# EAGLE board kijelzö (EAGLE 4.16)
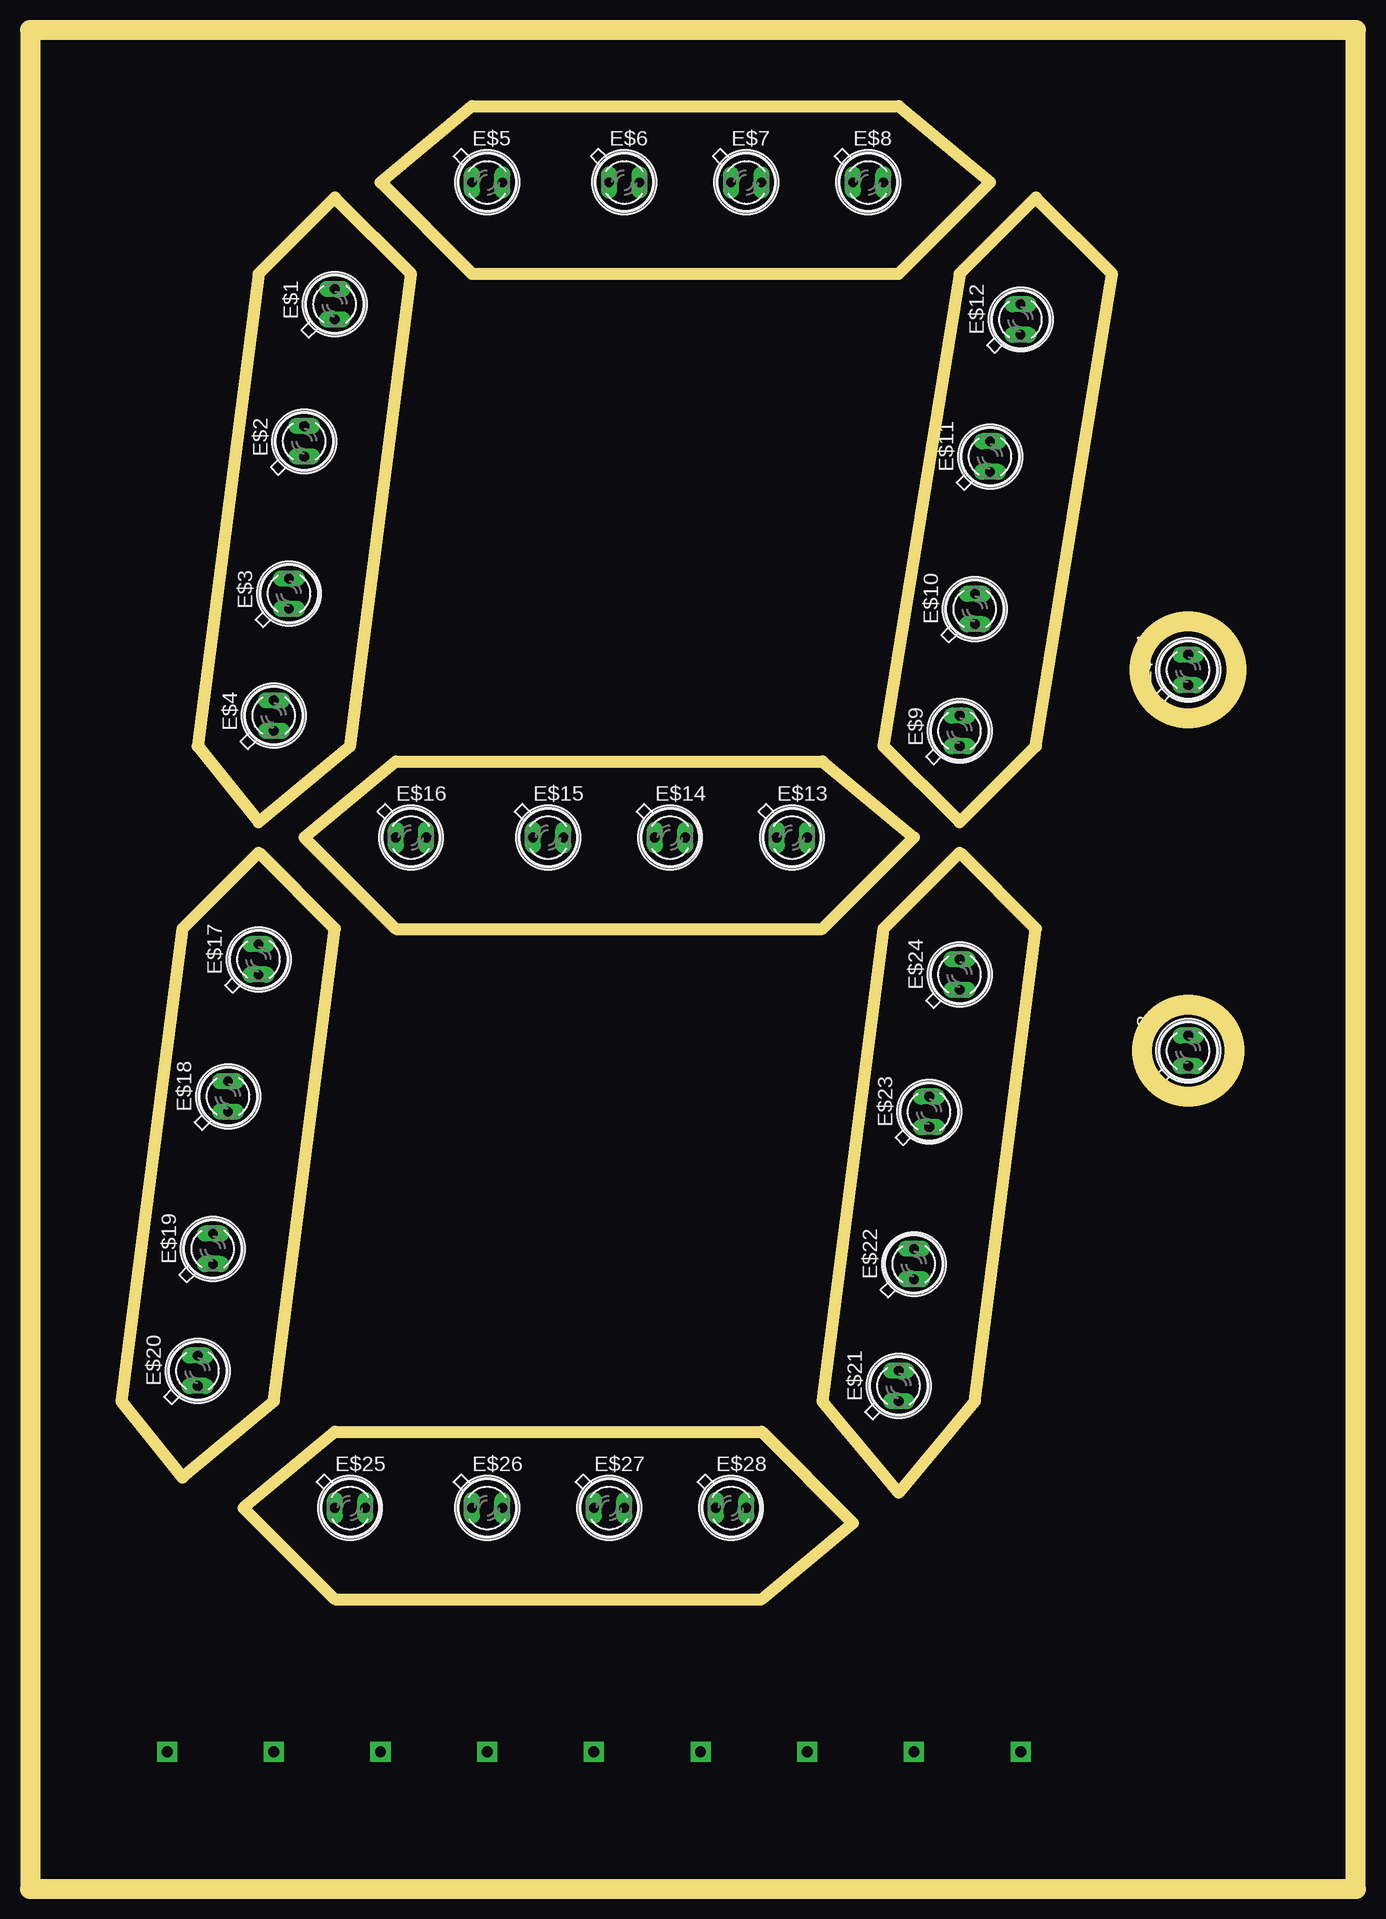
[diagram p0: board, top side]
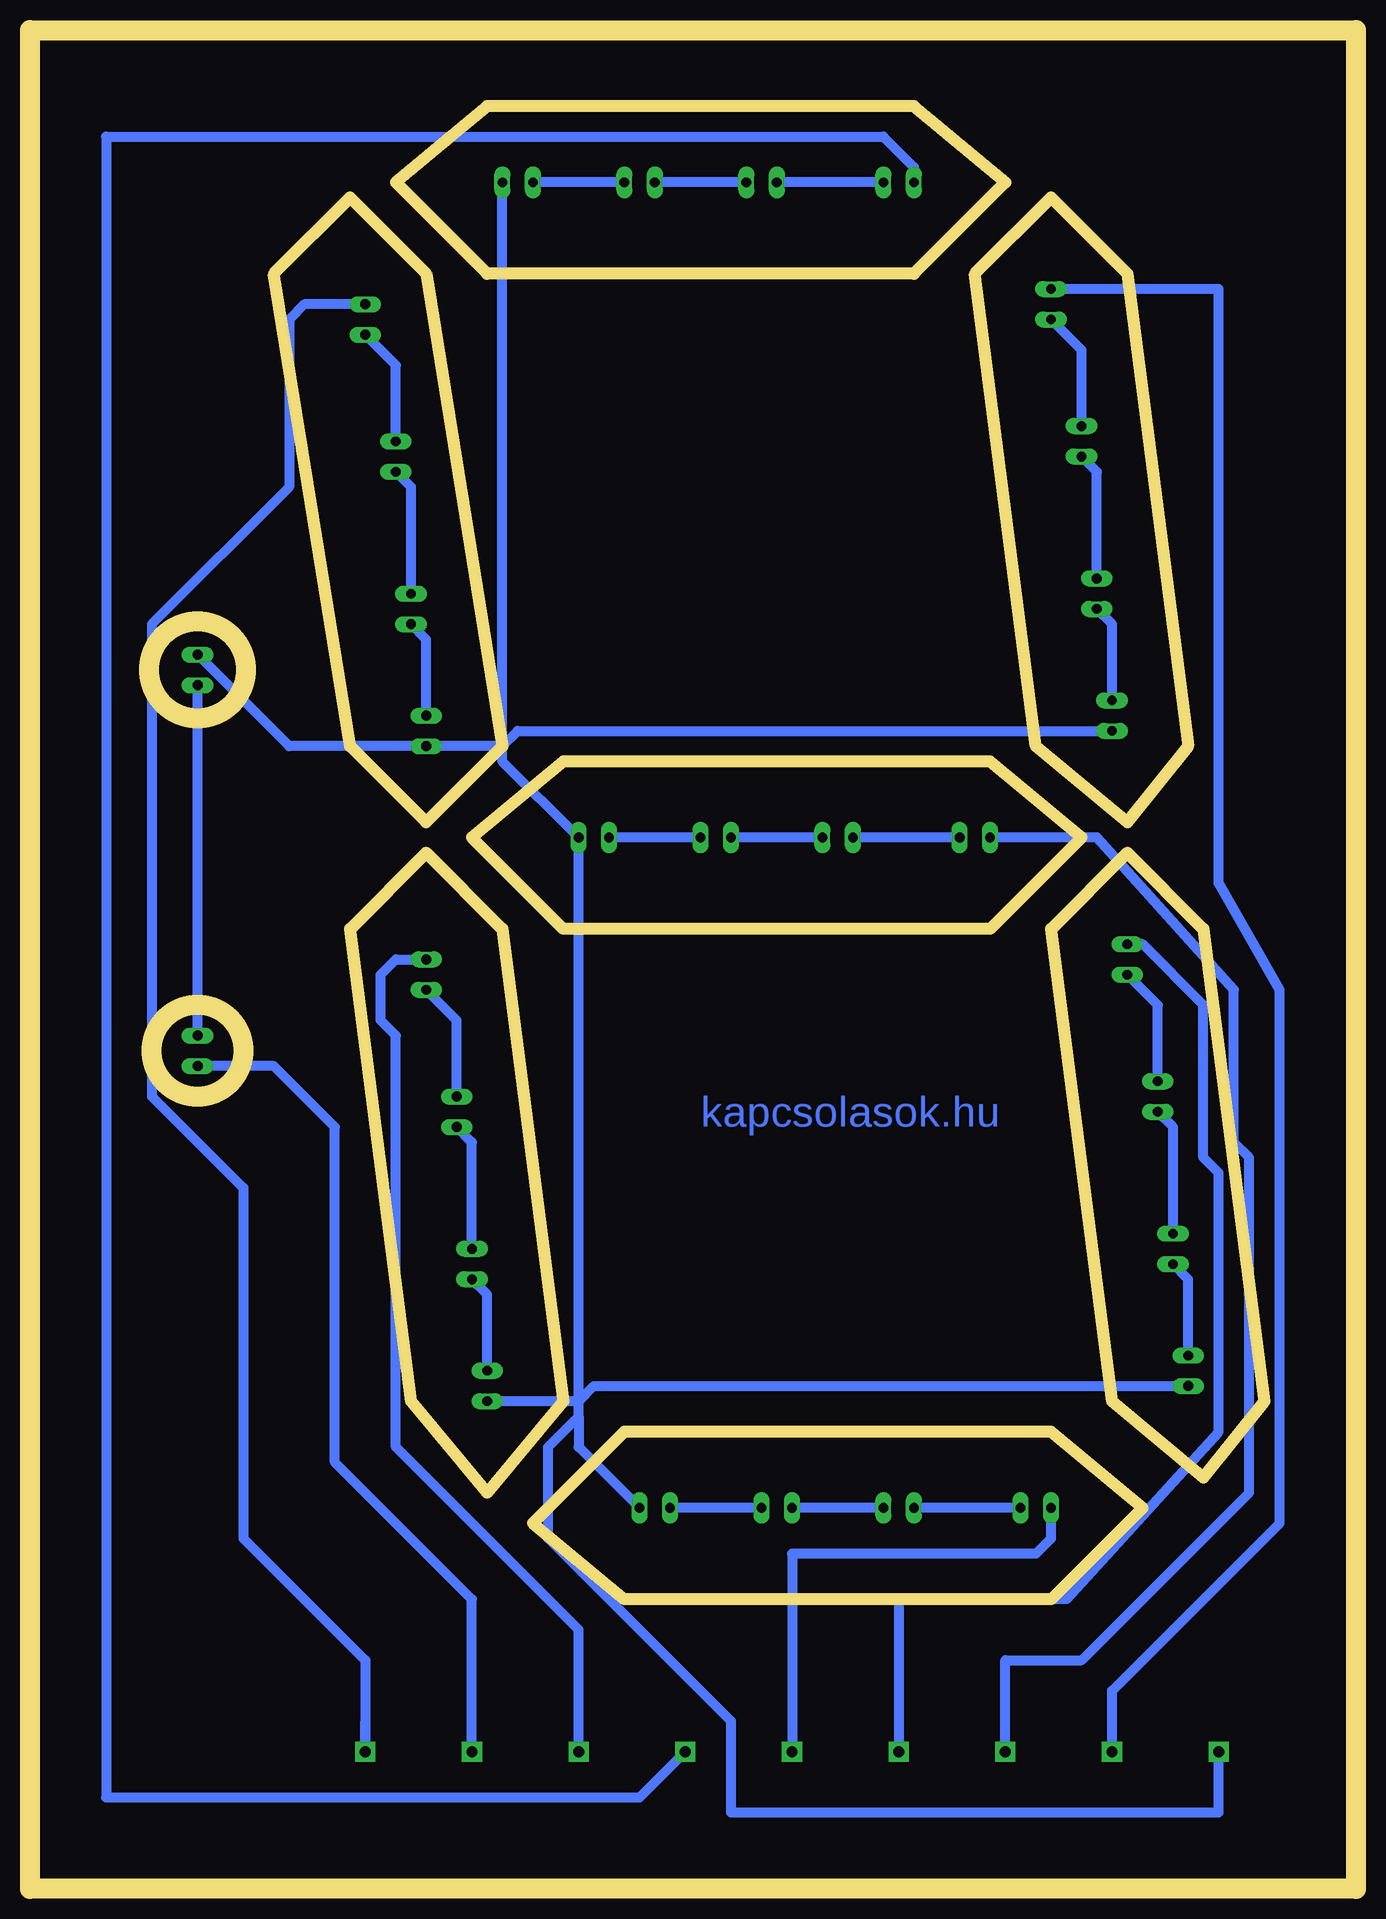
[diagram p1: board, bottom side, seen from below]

Size 110.49 x 154.94 mm. Coordinates in mm from the lower left corner, seen from the top.
Outline: 20.32,40.64 25.4,80.01 19.05,86.36 12.7,80.01 7.62,40.64 12.7,34.29 20.32,40.64
Outline: 26.67,95.25 31.75,134.62 25.4,140.97 19.05,134.62 13.97,95.25 19.05,88.9 26.67,95.25
Outline: 30.48,93.98 22.86,87.63 30.48,80.01 66.04,80.01 73.66,87.63 66.04,93.98 30.48,93.98
Outline: 78.74,40.64 83.82,80.01 77.47,86.36 71.12,80.01 66.04,40.64 72.39,33.02 78.74,40.64
Outline: 83.82,95.25 90.17,134.62 83.82,140.97 77.47,134.62 71.12,95.25 77.47,88.9 83.82,95.25
Outline: 36.83,148.59 29.21,142.24 36.83,134.62 72.39,134.62 80.01,142.24 72.39,148.59 36.83,148.59
Outline: 25.4,38.1 17.78,31.75 25.4,24.13 60.96,24.13 68.58,30.48 60.96,38.1 25.4,38.1
Outline: 0,0 110.49,0 110.49,154.94 0,154.94 0,0
Outline: circle at 96.52,101.6 radius 4.02
Outline: circle at 96.52,69.85 radius 3.81
Copper layers (1*16): Top 0.035mm / dielectric 1.5mm / Bottom 0.035mm
Design rules "default": minimum track width 10mil, minimum drill 24mil, track to track 8mil, track to pad 8mil, pad to pad 8mil, via to via 8mil, smd to smd 8mil, copper to edge 40mil, drill to drill 8mil, minimum pad ring 10mil, minimum via ring 8mil, stop-mask expansion 4mil, vias tented up to drill 0mil, thermal gap 10mil

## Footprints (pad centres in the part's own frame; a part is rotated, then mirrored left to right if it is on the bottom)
SFH480 = drill 0.813 long: A 1.27,0; K -1.27,0

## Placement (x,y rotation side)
E$1  [SFH480]  25.4,132.08 90 top
E$2  [SFH480]  22.86,120.65 90 top
E$3  [SFH480]  21.59,107.95 90 top
E$4  [SFH480]  20.32,97.79 90 top
E$5  [SFH480]  38.1,142.24 0 top
E$6  [SFH480]  49.53,142.24 0 top
E$7  [SFH480]  59.69,142.24 0 top
E$8  [SFH480]  69.85,142.24 0 top
E$9  [SFH480]  77.47,96.52 90 top
E$10  [SFH480]  78.74,106.68 90 top
E$11  [SFH480]  80.01,119.38 90 top
E$12  [SFH480]  82.55,130.81 90 top
E$13  [SFH480]  63.5,87.63 0 top
E$14  [SFH480]  53.34,87.63 0 top
E$15  [SFH480]  43.18,87.63 0 top
E$16  [SFH480]  31.75,87.63 0 top
E$17  [SFH480]  19.05,77.47 90 top
E$18  [SFH480]  16.51,66.04 90 top
E$19  [SFH480]  15.24,53.34 90 top
E$20  [SFH480]  13.97,43.18 90 top
E$21  [SFH480]  72.39,41.91 90 top
E$22  [SFH480]  73.66,52.07 90 top
E$23  [SFH480]  74.93,64.77 90 top
E$24  [SFH480]  77.47,76.2 90 top
E$25  [SFH480]  26.67,31.75 0 top
E$26  [SFH480]  38.1,31.75 0 top
E$27  [SFH480]  48.26,31.75 0 top
E$28  [SFH480]  58.42,31.75 0 top
E$33  [SFH480]  96.52,69.85 90 top
E$34  [SFH480]  96.52,101.6 90 top

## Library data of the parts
E$1-E$28 E$33 E$34 = led

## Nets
S$23: E$33.A E$34.K
S$28: E$33.K
S$37: E$12.A

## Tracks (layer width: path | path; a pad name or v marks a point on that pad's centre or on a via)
S$1
  Bottom 0.813: 27.94,31.75 36.83,31.75
S$2
  Bottom 0.813: 39.37,31.75 46.99,31.75
S$3
  Bottom 0.813: 49.53,31.75 57.15,31.75
S$4
  Bottom 0.813: 33.02,87.63 41.91,87.63
S$5
  Bottom 0.813: 44.45,87.63 52.07,87.63
S$6
  Bottom 0.813: 54.61,87.63 62.23,87.63
S$7
  Bottom 0.813: 39.37,142.24 48.26,142.24
S$8
  Bottom 0.813: 50.8,142.24 58.42,142.24
S$9
  Bottom 0.813: 60.96,142.24 68.58,142.24
S$10
  Bottom 0.813: 77.47,97.79 77.47,104.14 78.74,105.41
S$11
  Bottom 0.813: 78.74,107.95 78.74,116.84 80.01,118.11
S$12
  Bottom 0.813: 80.01,120.65 80.01,127 82.55,129.54
S$13
  Bottom 0.813: 20.32,99.06 20.32,105.41 21.59,106.68
S$14
  Bottom 0.813: 21.59,109.22 21.59,118.11 22.86,119.38
S$15
  Bottom 0.813: 22.86,121.92 22.86,128.27 25.4,130.81
S$16
  Bottom 0.813: 13.97,44.45 13.97,50.8 15.24,52.07
S$17
  Bottom 0.813: 15.24,54.61 15.24,63.5 16.51,64.77
S$18
  Bottom 0.813: 16.51,67.31 16.51,73.66 19.05,76.2
S$19
  Bottom 0.813: 72.39,43.18 72.39,49.53 73.66,50.8
S$20
  Bottom 0.813: 73.66,53.34 73.66,62.23 74.93,63.5
S$21
  Bottom 0.813: 74.93,66.04 74.93,72.39 77.47,74.93
S$22  (via drill 0.9 pad 1.68)
  Bottom 0.813: 71.12,95.25 71.12,142.24 | 71.12,95.25 71.12,93.98 64.77,87.63 64.77,40.64 | 64.77,39.37 64.77,40.64 | 64.77,39.37 64.77,36.83 59.69,31.75 | 64.77,40.64 72.39,40.64 | 20.32,96.52 69.85,96.52 71.12,95.25 | 13.97,41.91 63.5,41.91 64.77,40.64 | 71.12,95.25 88.9,95.25 96.52,102.87 | v11.43,11.43 11.43,6.35 52.07,6.35 52.07,13.97 67.31,29.21 67.31,36.83 64.77,39.37
S$23
  Bottom 0.813: E$33.A E$34.K
S$25  (via drill 0.9 pad 1.68)
  Bottom 0.813: 25.4,133.35 11.43,133.35 11.43,83.82 6.35,74.93 6.35,30.48 20.32,16.51 v20.32,11.43
S$26  (via drill 0.9 pad 1.68)
  Bottom 0.813: 30.48,87.63 21.59,87.63 10.16,74.93 10.16,62.23 8.89,60.96 8.89,33.02 22.86,19.05 29.21,19.05 v29.21,11.43
S$27  (via drill 0.9 pad 1.68)
  Bottom 0.813: v38.1,11.43 38.1,24.13 24.13,24.13 11.43,38.1 11.43,59.69 12.7,60.96 12.7,73.66 17.78,78.74 19.05,78.74
S$28  (via drill 0.9 pad 1.68)
  Bottom 0.813: v73.66,11.43 73.66,24.13 85.09,35.56 85.09,63.5 90.17,68.58 E$33.K
S$29  (via drill 0.9 pad 1.68)
  Bottom 0.813: v46.99,11.43 46.99,27.94 26.67,27.94 25.4,29.21 25.4,31.75
S$30  (via drill 0.9 pad 1.68)
  Bottom 0.813: 77.47,77.47 80.01,77.47 81.28,76.2 81.28,72.39 80.01,71.12 80.01,36.83 64.77,21.59 v64.77,11.43
S$31  (via drill 0.9 pad 1.68)
  Bottom 0.813: 36.83,142.24 36.83,143.51 39.37,146.05 104.14,146.05 104.14,7.62 59.69,7.62 v55.88,11.43
S$37  (via drill 0.9 pad 1.68)
  Bottom 0.813: 82.55,13.97 v82.55,11.43 82.55,19.05 92.71,29.21 92.71,58.42 100.33,66.04 100.33,105.41 88.9,116.84 88.9,130.81 87.63,132.08 E$12.A

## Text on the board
Bottom: kapcsolasok.hu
